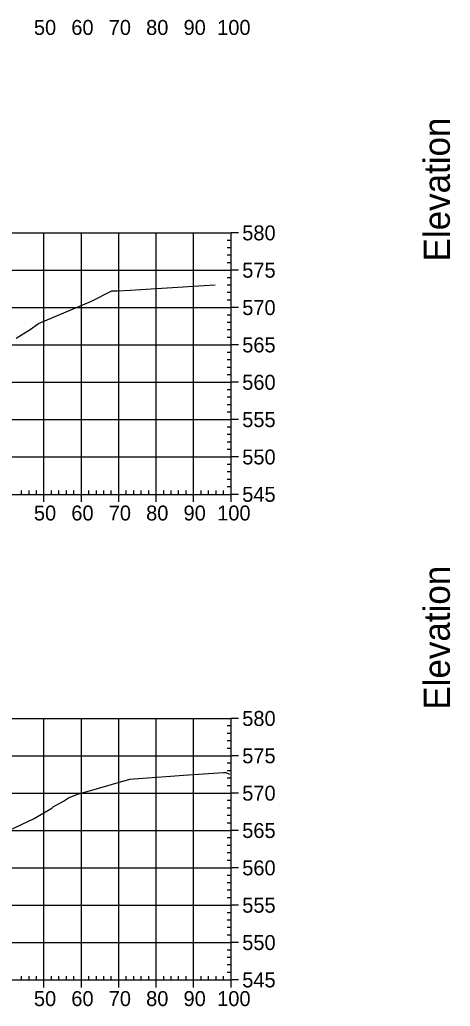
# Model space of a CAD drawing. Extents: x 704834 to 709892, y 372981 to 377533.
# Drawn here: x 708723.4 to 708838.5, y 376453.8 to 376717.9 of the extents above; entities that cross this region are included whole.
import ezdxf

# ---------------------------------------------------------------- set-up
doc = ezdxf.new("R2010")
doc.units = 0
for name, color, linetype in [('57', 7, 'Continuous'), ('60', 7, 'Continuous'), ('Existing', 7, 'Continuous')]:
    doc.layers.add(name, color=color, linetype=linetype)

msp = doc.modelspace()

# ---------------------------------------------------------------- linework, layer by layer
at = {"layer": '57'}
for p, q in [((708579.91, 376660.82), (708779.91, 376660.82)), ((708729.91, 376590.82), (708729.91, 376660.82)), ((708739.91, 376590.82), (708739.91, 376660.82)), ((708749.91, 376590.82), (708749.91, 376660.82)), ((708759.91, 376590.82), (708759.91, 376660.82)), ((708769.91, 376590.82), (708769.91, 376660.82)), ((708779.91, 376590.82), (708779.91, 376660.82)), ((708779.91, 376590.82), (708779.91, 376660.82)), ((708781.91, 376660.82), (708779.91, 376660.82)), ((708779.91, 376658.82), (708778.91, 376658.82)), ((708779.91, 376656.82), (708778.91, 376656.82)), ((708779.91, 376654.82), (708778.91, 376654.82)), ((708779.91, 376652.82), (708778.91, 376652.82)), ((708579.91, 376650.82), (708779.91, 376650.82)), ((708779.91, 376648.82), (708778.91, 376648.82)), ((708781.91, 376650.82), (708779.91, 376650.82)), ((708779.91, 376646.82), (708778.91, 376646.82)), ((708779.91, 376644.82), (708778.91, 376644.82)), ((708579.91, 376640.82), (708779.91, 376640.82)), ((708779.91, 376642.82), (708778.91, 376642.82)), ((708781.91, 376640.82), (708779.91, 376640.82)), ((708779.91, 376638.82), (708778.91, 376638.82)), ((708779.91, 376636.82), (708778.91, 376636.82)), ((708779.91, 376634.82), (708778.91, 376634.82)), ((708779.91, 376632.82), (708778.91, 376632.82)), ((708579.91, 376630.82), (708779.91, 376630.82)), ((708781.91, 376630.82), (708779.91, 376630.82)), ((708779.91, 376628.82), (708778.91, 376628.82)), ((708779.91, 376626.82), (708778.91, 376626.82)), ((708779.91, 376624.82), (708778.91, 376624.82)), ((708779.91, 376622.82), (708778.91, 376622.82)), ((708579.91, 376620.82), (708779.91, 376620.82)), ((708781.91, 376620.82), (708779.91, 376620.82)), ((708779.91, 376618.82), (708778.91, 376618.82)), ((708779.91, 376616.82), (708778.91, 376616.82)), ((708779.91, 376614.82), (708778.91, 376614.82)), ((708779.91, 376612.82), (708778.91, 376612.82)), ((708579.91, 376610.82), (708779.91, 376610.82)), ((708781.91, 376610.82), (708779.91, 376610.82)), ((708779.91, 376608.82), (708778.91, 376608.82)), ((708779.91, 376606.82), (708778.91, 376606.82)), ((708779.91, 376604.82), (708778.91, 376604.82)), ((708779.91, 376602.82), (708778.91, 376602.82)), ((708579.91, 376600.82), (708779.91, 376600.82)), ((708779.91, 376598.82), (708778.91, 376598.82)), ((708781.91, 376600.82), (708779.91, 376600.82)), ((708779.91, 376596.82), (708778.91, 376596.82)), ((708779.91, 376594.82), (708778.91, 376594.82)), ((708579.91, 376590.82), (708779.91, 376590.82)), ((708579.91, 376590.82), (708779.91, 376590.82)), ((708723.91, 376590.82), (708723.91, 376591.82)), ((708725.91, 376590.82), (708725.91, 376591.82)), ((708727.91, 376590.82), (708727.91, 376591.82)), ((708729.91, 376588.82), (708729.91, 376590.82)), ((708731.91, 376590.82), (708731.91, 376591.82)), ((708733.91, 376590.82), (708733.91, 376591.82)), ((708735.91, 376590.82), (708735.91, 376591.82)), ((708737.91, 376590.82), (708737.91, 376591.82)), ((708739.91, 376588.82), (708739.91, 376590.82)), ((708741.91, 376590.82), (708741.91, 376591.82)), ((708743.91, 376590.82), (708743.91, 376591.82)), ((708745.91, 376590.82), (708745.91, 376591.82)), ((708747.91, 376590.82), (708747.91, 376591.82)), ((708749.91, 376588.82), (708749.91, 376590.82)), ((708751.91, 376590.82), (708751.91, 376591.82)), ((708753.91, 376590.82), (708753.91, 376591.82)), ((708755.91, 376590.82), (708755.91, 376591.82)), ((708757.91, 376590.82), (708757.91, 376591.82)), ((708759.91, 376588.82), (708759.91, 376590.82)), ((708761.91, 376590.82), (708761.91, 376591.82)), ((708763.91, 376590.82), (708763.91, 376591.82)), ((708765.91, 376590.82), (708765.91, 376591.82)), ((708767.91, 376590.82), (708767.91, 376591.82)), ((708769.91, 376588.82), (708769.91, 376590.82)), ((708771.91, 376590.82), (708771.91, 376591.82)), ((708773.91, 376590.82), (708773.91, 376591.82)), ((708775.91, 376590.82), (708775.91, 376591.82)), ((708777.91, 376590.82), (708777.91, 376591.82)), ((708779.91, 376592.82), (708778.91, 376592.82)), ((708779.91, 376588.82), (708779.91, 376590.82)), ((708781.91, 376590.82), (708779.91, 376590.82)), ((708579.91, 376530.82), (708779.91, 376530.82)), ((708729.91, 376460.82), (708729.91, 376530.82)), ((708739.91, 376460.82), (708739.91, 376530.82)), ((708749.91, 376460.82), (708749.91, 376530.82)), ((708759.91, 376460.82), (708759.91, 376530.82)), ((708769.91, 376460.82), (708769.91, 376530.82)), ((708779.91, 376460.82), (708779.91, 376530.82)), ((708779.91, 376460.82), (708779.91, 376530.82)), ((708781.91, 376530.82), (708779.91, 376530.82)), ((708779.91, 376528.82), (708778.91, 376528.82)), ((708779.91, 376526.82), (708778.91, 376526.82)), ((708779.91, 376524.82), (708778.91, 376524.82)), ((708779.91, 376522.82), (708778.91, 376522.82)), ((708579.91, 376520.82), (708779.91, 376520.82)), ((708781.91, 376520.82), (708779.91, 376520.82)), ((708779.91, 376518.82), (708778.91, 376518.82)), ((708779.91, 376516.82), (708778.91, 376516.82)), ((708779.91, 376514.82), (708778.91, 376514.82)), ((708779.91, 376512.82), (708778.91, 376512.82)), ((708579.91, 376510.82), (708779.91, 376510.82)), ((708779.91, 376508.82), (708778.91, 376508.82)), ((708781.91, 376510.82), (708779.91, 376510.82)), ((708779.91, 376506.82), (708778.91, 376506.82)), ((708779.91, 376504.82), (708778.91, 376504.82)), ((708579.91, 376500.82), (708779.91, 376500.82)), ((708779.91, 376502.82), (708778.91, 376502.82)), ((708781.91, 376500.82), (708779.91, 376500.82)), ((708779.91, 376498.82), (708778.91, 376498.82)), ((708779.91, 376496.82), (708778.91, 376496.82)), ((708779.91, 376494.82), (708778.91, 376494.82)), ((708779.91, 376492.82), (708778.91, 376492.82)), ((708579.91, 376490.82), (708779.91, 376490.82)), ((708781.91, 376490.82), (708779.91, 376490.82)), ((708779.91, 376488.82), (708778.91, 376488.82)), ((708779.91, 376486.82), (708778.91, 376486.82)), ((708779.91, 376484.82), (708778.91, 376484.82)), ((708779.91, 376482.82), (708778.91, 376482.82)), ((708579.91, 376480.82), (708779.91, 376480.82)), ((708781.91, 376480.82), (708779.91, 376480.82)), ((708779.91, 376478.82), (708778.91, 376478.82)), ((708779.91, 376476.82), (708778.91, 376476.82)), ((708779.91, 376474.82), (708778.91, 376474.82)), ((708779.91, 376472.82), (708778.91, 376472.82)), ((708579.91, 376470.82), (708779.91, 376470.82)), ((708781.91, 376470.82), (708779.91, 376470.82)), ((708779.91, 376468.82), (708778.91, 376468.82)), ((708779.91, 376466.82), (708778.91, 376466.82)), ((708779.91, 376464.82), (708778.91, 376464.82)), ((708723.91, 376460.82), (708723.91, 376461.82)), ((708725.91, 376460.82), (708725.91, 376461.82)), ((708727.91, 376460.82), (708727.91, 376461.82)), ((708731.91, 376460.82), (708731.91, 376461.82)), ((708733.91, 376460.82), (708733.91, 376461.82)), ((708735.91, 376460.82), (708735.91, 376461.82)), ((708737.91, 376460.82), (708737.91, 376461.82)), ((708741.91, 376460.82), (708741.91, 376461.82)), ((708743.91, 376460.82), (708743.91, 376461.82)), ((708745.91, 376460.82), (708745.91, 376461.82)), ((708747.91, 376460.82), (708747.91, 376461.82)), ((708751.91, 376460.82), (708751.91, 376461.82)), ((708753.91, 376460.82), (708753.91, 376461.82)), ((708755.91, 376460.82), (708755.91, 376461.82)), ((708757.91, 376460.82), (708757.91, 376461.82)), ((708761.91, 376460.82), (708761.91, 376461.82)), ((708763.91, 376460.82), (708763.91, 376461.82)), ((708765.91, 376460.82), (708765.91, 376461.82)), ((708767.91, 376460.82), (708767.91, 376461.82)), ((708771.91, 376460.82), (708771.91, 376461.82)), ((708773.91, 376460.82), (708773.91, 376461.82)), ((708775.91, 376460.82), (708775.91, 376461.82)), ((708777.91, 376460.82), (708777.91, 376461.82)), ((708779.91, 376462.82), (708778.91, 376462.82)), ((708579.91, 376460.82), (708779.91, 376460.82)), ((708579.91, 376460.82), (708779.91, 376460.82)), ((708729.91, 376458.82), (708729.91, 376460.82)), ((708739.91, 376458.82), (708739.91, 376460.82)), ((708749.91, 376458.82), (708749.91, 376460.82)), ((708759.91, 376458.82), (708759.91, 376460.82)), ((708769.91, 376458.82), (708769.91, 376460.82)), ((708779.91, 376458.82), (708779.91, 376460.82)), ((708781.91, 376460.82), (708779.91, 376460.82))]:
    msp.add_line(p, q, dxfattribs=at)
at = {"layer": 'Existing'}
for points in [[(708722.51, 376632.62), (708726.18, 376634.99), (708728.43, 376636.53), (708742.62, 376642.53), (708748.06, 376645.33), (708748.27, 376645.32), (708749.51, 376645.27), (708752.91, 376645.52), (708772.74, 376646.77), (708775.68, 376646.93)], [(708720.71, 376500.91), (708727.07, 376503.93), (708731.99, 376506.78), (708732.41, 376507.2), (708735.1, 376508.68), (708736.49, 376509.58), (708739.34, 376510.74), (708739.57, 376510.73), (708752.89, 376514.55), (708753.91, 376514.62), (708763.72, 376515.39), (708767.19, 376515.6), (708777.88, 376516.37), (708778.56, 376516.39), (708779.48, 376515.88)]]:
    msp.add_lwpolyline(points, dxfattribs=at)

# ---------------------------------------------------------------- texts
at = {"layer": '57'}
for s, p in [('50', (708727.22, 376713.82)), ('60', (708737.22, 376713.82)), ('70', (708747.22, 376713.82)), ('80', (708757.22, 376713.82)), ('90', (708767.22, 376713.82)), ('100', (708776.21, 376713.82)), ('580', (708782.91, 376658.82)), ('575', (708782.91, 376648.82)), ('570', (708782.91, 376638.82)), ('565', (708782.91, 376628.82)), ('560', (708782.91, 376618.82)), ('555', (708782.91, 376608.82)), ('550', (708782.91, 376598.82)), ('545', (708782.91, 376588.82)), ('50', (708727.22, 376583.82)), ('60', (708737.22, 376583.82)), ('70', (708747.22, 376583.82)), ('80', (708757.22, 376583.82)), ('90', (708767.22, 376583.82)), ('100', (708776.21, 376583.82)), ('580', (708782.91, 376528.82)), ('575', (708782.91, 376518.82)), ('570', (708782.91, 376508.82)), ('565', (708782.91, 376498.82)), ('560', (708782.91, 376488.82)), ('555', (708782.91, 376478.82)), ('550', (708782.91, 376468.82)), ('545', (708782.91, 376458.82)), ('50', (708727.22, 376453.82)), ('60', (708737.22, 376453.82)), ('70', (708747.22, 376453.82)), ('80', (708757.22, 376453.82)), ('90', (708767.22, 376453.82)), ('100', (708776.21, 376453.82))]:
    msp.add_text(s, height=4, dxfattribs=at).set_placement(p)
at = {"layer": '60'}
for p in [(708838.41, 376653.18), (708838.41, 376533.18)]:
    msp.add_text('Elevation', height=7, rotation=90, dxfattribs=at).set_placement(p)

doc.saveas('drawing.dxf')
